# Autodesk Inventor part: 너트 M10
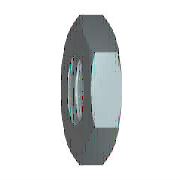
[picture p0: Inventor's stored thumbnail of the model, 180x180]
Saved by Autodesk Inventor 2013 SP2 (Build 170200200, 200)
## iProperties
IsCustomPart: 1
Created: 2012-02
Part Number: 너트 M10
Material: 스테인리스강
Description: 미터법 정밀 피치 스레드가 있는 6각 가는 너트(모따기됨)
Document SubType Name: Modeling
Standard: ISO 8675
Designer: mduedu
Standard Revision: Second edition 1999-08-15
Standards Organization: ISO
Language: ko-KR
Size Designation: M10 x 1
Categories: <MemberInstance><Categories><Category DisplayName="조임쇠" InternalName="e4da775c-781d-43d5-af7c-5136215cf5a6" Mnemonic="FSTN"><Category DisplayName="너트" InternalN
Density: 8.08 g/cm^3
Author: mduedu
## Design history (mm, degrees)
sketch "스케치1"
  geometry: L1 (-9.238, 0)-(-4.619, 8); L2 (-4.619, 8)-(4.619, 8); L3 (4.619, 8)-(9.238, 0); L4 (9.238, 0)-(4.619, -8); L5 (4.619, -8)-(-4.619, -8); L6 (-4.619, -8)-(-9.238, 0); 2 further points
  constraints: 12 end point, 1 coincident, 1 horizontal, 11 other
  dimensions: "d0" = 18.47521 distance of L3.end L1.start (= 1.1547 x SW)
extrude "본체" new body sketch "스케치1" distance "d1" = 5 (= KOH); taper "d2" = 0 deg
sketch "스케치2"
  geometry: L1 (0, 4.619)-(0, 9.238) reference; L2 (0, 9.238)-(5, 9.238) reference; L3 (5, 4.619)-(5, 9.238) reference; L4 (-1, 0)-(6, 0) reference; L5 (1.11, 9.238)-(0, 7.315); L6 (3.89, 9.238)-(5, 7.315)
  constraints: 4 end point, 4 point on line
  dimensions: "d3" = 30 deg angle of L1 L5 (= ANG1); "d4" = 30 deg angle of L3 L6 (= ANG2); "d5" = 14.63 diameter of L5.end L4 (= SW0); "d6" = 14.63 diameter of L6.end L4 (= SW01)
revolve "모따기1" sketch "스케치2" stored, may be unused: angle "d7" = 90 deg
sketch "스케치3"
  geometry: 4 further points
  constraints: 1 coincident, 1 other
hole "스레드" sketch "스케치3" at (0, 0) diameter "d25" = 8.91747; stored, may be unused: countersink angle "d29" = 82 deg, drill point angle "d31" = 118 deg; dims "d26" = 6, "d27" = 4, "d28" = 2, "d30" = 8
workaxis "Work Axis1"
workplane "Work Plane1"
body "Solid1"
chamfer "모따기2" distance "d8" = 0.54127 (= -0.5 x GD1 + 0.5 x NND); stored, may be unused: angle "d9" = 30 deg, second distance "d40" = 0.54127 (= -0.5 x GD1 + 0.5 x NND)
chamfer "모따기3" distance "d10" = 0.54127 (= -0.5 x GD1 + 0.5 x NND); stored, may be unused: angle "d11" = 30 deg, second distance "d41" = 0.54127 (= -0.5 x GD1 + 0.5 x NND)
other parameters: "ANG1" = 30 deg [user parameter; used in 1 equation term], "ANG2" = 30 deg [user parameter; used in 1 equation term], "KOH" = 5 [user parameter; used in 1 equation term], "SW" = 16 [user parameter; used in 1 equation term], "SW0" = 14.63 [user parameter; used in 2 equation terms], "SW01" = 14.63 (= SW0) [user parameter; used in 1 equation term], "GD1" = 8.91747 (computed from THREADDIA, PTC, TOA) [user parameter; used in 4 equation terms], "d13" = 0, "d14" = 0, "d39" = 0, "d42" = 0, "GUL" = 0.54127 (= 0.541266 x PTC) [user parameter], "TOA" = 30 deg [user parameter; used in 1 equation term], "PTC" = 1 [user parameter; used in 4 equation terms], "E0" = 17.77 [user parameter], "GAL" = 0.54127 (= 0.541266 x PTC) [user parameter]
